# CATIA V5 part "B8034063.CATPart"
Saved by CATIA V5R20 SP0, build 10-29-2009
Part number: B8034063
Revision: 4
Definition: design
Nomenclature: B8034063
Source: made
Description: NOT SPECIFIED
Bounding box of the stored display mesh (mm): x -30 to 30, y -30 to 30, z 0 to 63
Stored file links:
  C:\Users\Utente\Desktop\3D files B803\B8034063.CATPart
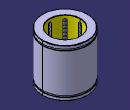
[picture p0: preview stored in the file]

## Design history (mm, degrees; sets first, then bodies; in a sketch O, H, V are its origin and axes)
Body1 "MANIFOLD_SOLID_BREP #38" (main body)
  Solid1: solid without history
Body2 "MANIFOLD_SOLID_BREP #76"
  Solid2: solid without history
Body3 "MANIFOLD_SOLID_BREP #114"
  Solid3: solid without history
Body4 "MANIFOLD_SOLID_BREP #152"
  Solid4: solid without history
Body5 "MANIFOLD_SOLID_BREP #190"
  Solid5: solid without history
Body6 "MANIFOLD_SOLID_BREP #228"
  Solid6: solid without history
Body7 "MANIFOLD_SOLID_BREP #266"
  Solid7: solid without history
Body8 "MANIFOLD_SOLID_BREP #304"
  Solid8: solid without history
Body9 "MANIFOLD_SOLID_BREP #2444"
  Solid9: solid without history
Body10 "MANIFOLD_SOLID_BREP #2482"
  Solid10: solid without history
Body11 "MANIFOLD_SOLID_BREP #2520"
  Solid11: solid without history
Body12 "MANIFOLD_SOLID_BREP #2558"
  Solid12: solid without history
Body13 "MANIFOLD_SOLID_BREP #2596"
  Solid13: solid without history
Body14 "MANIFOLD_SOLID_BREP #2634"
  Solid14: solid without history
Body15 "MANIFOLD_SOLID_BREP #2672"
  Solid15: solid without history
Body16 "MANIFOLD_SOLID_BREP #2710"
  Solid16: solid without history
Body17 "MANIFOLD_SOLID_BREP #2748"
  Solid17: solid without history
Body18 "MANIFOLD_SOLID_BREP #2786"
  Solid18: solid without history
Body19 "MANIFOLD_SOLID_BREP #2824"
  Solid19: solid without history
Body20 "MANIFOLD_SOLID_BREP #2862"
  Solid20: solid without history
Body21 "MANIFOLD_SOLID_BREP #2900"
  Solid21: solid without history
Body22 "MANIFOLD_SOLID_BREP #2938"
  Solid22: solid without history
Body23 "MANIFOLD_SOLID_BREP #2976"
  Solid23: solid without history
Body24 "MANIFOLD_SOLID_BREP #3014"
  Solid24: solid without history
Body25 "MANIFOLD_SOLID_BREP #3052"
  Solid25: solid without history
Body26 "MANIFOLD_SOLID_BREP #3090"
  Solid26: solid without history
Body27 "MANIFOLD_SOLID_BREP #3128"
  Solid27: solid without history
Body28 "MANIFOLD_SOLID_BREP #3166"
  Solid28: solid without history
Body29 "MANIFOLD_SOLID_BREP #3204"
  Solid29: solid without history
Body30 "MANIFOLD_SOLID_BREP #3242"
  Solid30: solid without history
Body31 "MANIFOLD_SOLID_BREP #3280"
  Solid31: solid without history
Body32 "MANIFOLD_SOLID_BREP #3318"
  Solid32: solid without history
Body33 "MANIFOLD_SOLID_BREP #3356"
  Solid33: solid without history
Body34 "MANIFOLD_SOLID_BREP #3394"
  Solid34: solid without history
Body35 "MANIFOLD_SOLID_BREP #3432"
  Solid35: solid without history
Body36 "MANIFOLD_SOLID_BREP #3470"
  Solid36: solid without history
Body37 "MANIFOLD_SOLID_BREP #3508"
  Solid37: solid without history
Body38 "MANIFOLD_SOLID_BREP #3546"
  Solid38: solid without history
Body39 "MANIFOLD_SOLID_BREP #3584"
  Solid39: solid without history
Body40 "MANIFOLD_SOLID_BREP #3622"
  Solid40: solid without history
Body41 "MANIFOLD_SOLID_BREP #3660"
  Solid41: solid without history
Body42 "MANIFOLD_SOLID_BREP #3698"
  Solid42: solid without history
Body43 "MANIFOLD_SOLID_BREP #3736"
  Solid43: solid without history
Body44 "MANIFOLD_SOLID_BREP #3774"
  Solid44: solid without history
Body45 "MANIFOLD_SOLID_BREP #3812"
  Solid45: solid without history
Body46 "MANIFOLD_SOLID_BREP #3850"
  Solid46: solid without history
Body47 "MANIFOLD_SOLID_BREP #3888"
  Solid47: solid without history
Body48 "MANIFOLD_SOLID_BREP #3926"
  Solid48: solid without history
Body49 "MANIFOLD_SOLID_BREP #3964"
  Solid49: solid without history
Body50 "MANIFOLD_SOLID_BREP #4002"
  Solid50: solid without history
Body51 "MANIFOLD_SOLID_BREP #4040"
  Solid51: solid without history
Body52 "MANIFOLD_SOLID_BREP #4078"
  Solid52: solid without history
Body53 "MANIFOLD_SOLID_BREP #4116"
  Solid53: solid without history
Body54 "MANIFOLD_SOLID_BREP #4154"
  Solid54: solid without history
Body55 "MANIFOLD_SOLID_BREP #4192"
  Solid55: solid without history
Body56 "MANIFOLD_SOLID_BREP #4230"
  Solid56: solid without history
Body57 "MANIFOLD_SOLID_BREP #4268"
  Solid57: solid without history
Body58 "MANIFOLD_SOLID_BREP #4306"
  Solid58: solid without history
Body59 "MANIFOLD_SOLID_BREP #4344"
  Solid59: solid without history
Body60 "MANIFOLD_SOLID_BREP #4382"
  Solid60: solid without history
Body61 "MANIFOLD_SOLID_BREP #4420"
  Solid61: solid without history
Body62 "MANIFOLD_SOLID_BREP #4458"
  Solid62: solid without history
Body63 "MANIFOLD_SOLID_BREP #4496"
  Solid63: solid without history
Body64 "MANIFOLD_SOLID_BREP #4534"
  Solid64: solid without history
Body65 "MANIFOLD_SOLID_BREP #4572"
  Solid65: solid without history
Body66 "MANIFOLD_SOLID_BREP #4610"
  Solid66: solid without history
Body67 "MANIFOLD_SOLID_BREP #4648"
  Solid67: solid without history
Body68 "MANIFOLD_SOLID_BREP #4686"
  Solid68: solid without history
Body69 "MANIFOLD_SOLID_BREP #4724"
  Solid69: solid without history
Body70 "MANIFOLD_SOLID_BREP #4762"
  Solid70: solid without history
Body71 "MANIFOLD_SOLID_BREP #4800"
  Solid71: solid without history
Body72 "MANIFOLD_SOLID_BREP #4838"
  Solid72: solid without history
Body73 "MANIFOLD_SOLID_BREP #4876"
  Solid73: solid without history
Body74 "MANIFOLD_SOLID_BREP #4914"
  Solid74: solid without history
Body75 "MANIFOLD_SOLID_BREP #4952"
  Solid75: solid without history
Body76 "MANIFOLD_SOLID_BREP #4990"
  Solid76: solid without history
Body77 "MANIFOLD_SOLID_BREP #5028"
  Solid77: solid without history
Body78 "MANIFOLD_SOLID_BREP #5066"
  Solid78: solid without history
Body79 "MANIFOLD_SOLID_BREP #5104"
  Solid79: solid without history
Body80 "MANIFOLD_SOLID_BREP #5142"
  Solid80: solid without history
Body81 "MANIFOLD_SOLID_BREP #5180"
  Solid81: solid without history
Body82 "MANIFOLD_SOLID_BREP #5218"
  Solid82: solid without history
Body83 "MANIFOLD_SOLID_BREP #5256"
  Solid83: solid without history
Body84 "MANIFOLD_SOLID_BREP #5294"
  Solid84: solid without history
Body85 "MANIFOLD_SOLID_BREP #5332"
  Solid85: solid without history
Body86 "MANIFOLD_SOLID_BREP #5370"
  Solid86: solid without history
Body87 "MANIFOLD_SOLID_BREP #5408"
  Solid87: solid without history
Body88 "MANIFOLD_SOLID_BREP #5446"
  Solid88: solid without history
Body89 "MANIFOLD_SOLID_BREP #5484"
  Solid89: solid without history
Body90 "MANIFOLD_SOLID_BREP #5522"
  Solid90: solid without history
Body91 "MANIFOLD_SOLID_BREP #5560"
  Solid91: solid without history
Body92 "MANIFOLD_SOLID_BREP #5598"
  Solid92: solid without history
Body93 "MANIFOLD_SOLID_BREP #5636"
  Solid93: solid without history
Body94 "MANIFOLD_SOLID_BREP #5674"
  Solid94: solid without history
Body95 "MANIFOLD_SOLID_BREP #5712"
  Solid95: solid without history
Body96 "MANIFOLD_SOLID_BREP #5750"
  Solid96: solid without history
Body97 "MANIFOLD_SOLID_BREP #5788"
  Solid97: solid without history
Body98 "MANIFOLD_SOLID_BREP #5826"
  Solid98: solid without history
Body99 "MANIFOLD_SOLID_BREP #5864"
  Solid99: solid without history
Body100 "MANIFOLD_SOLID_BREP #5902"
  Solid100: solid without history
Body101 "MANIFOLD_SOLID_BREP #5940"
  Solid101: solid without history
Body102 "MANIFOLD_SOLID_BREP #5978"
  Solid102: solid without history
Body103 "MANIFOLD_SOLID_BREP #6016"
  Solid103: solid without history
Body104 "MANIFOLD_SOLID_BREP #6054"
  Solid104: solid without history
Body105 "MANIFOLD_SOLID_BREP #6092"
  Solid105: solid without history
